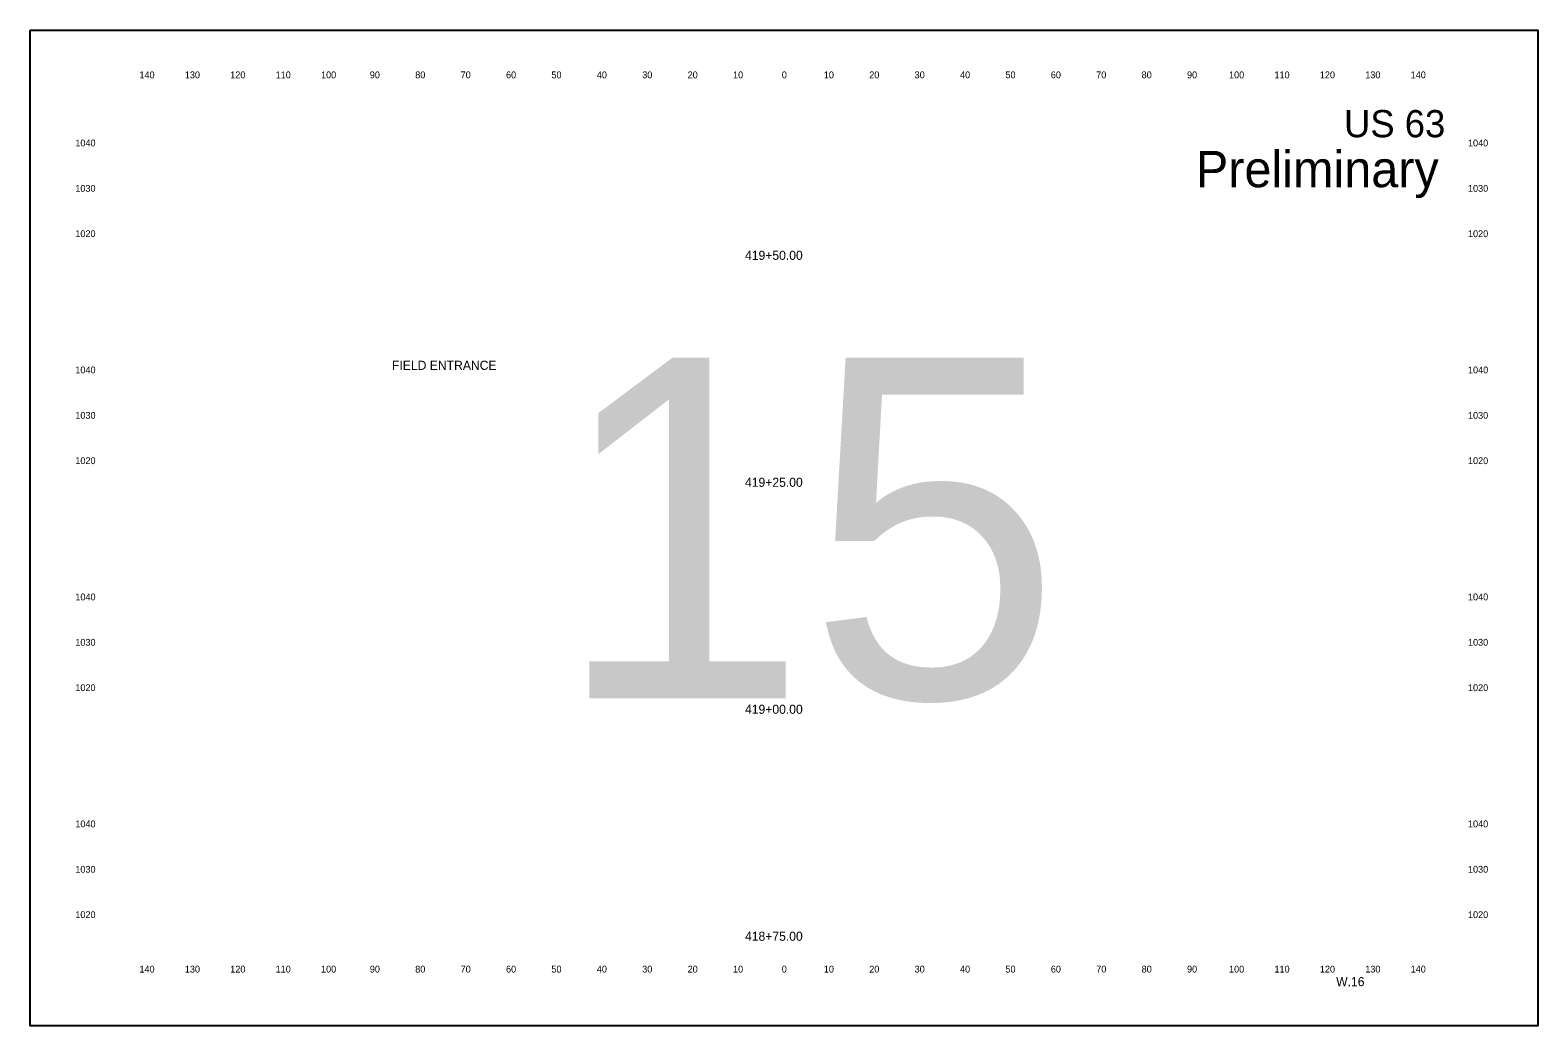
# Model space of a CAD drawing. Extents: x 10123 to 17295, y 9730 to 10181.
# Drawn here: x 15163.2 to 15495.3, y 9730.3 to 9949.6 of the extents above; entities that cross this region are included whole.
import ezdxf

# ---------------------------------------------------------------- set-up
doc = ezdxf.new("R2010")
doc.units = 0
for name, color, linetype in [('dsnTextCpn', 7, 'Continuous'), ('dsnTextCpnTitleSheetLocDesc', 7, 'Continuous'), ('dsnTextCpnTitleSheetPIN', 7, 'Continuous'), ('dsnTextCpnTitleSheetWorkType', 7, 'Continuous')]:
    doc.layers.add(name, color=color, linetype=linetype)

msp = doc.modelspace()

# ---------------------------------------------------------------- linework, layer by layer
at = {"layer": 'dsnTextCpnTitleSheetWorkType'}
msp.add_lwpolyline([(15163.21, 9949.6), (15495.29, 9949.6), (15495.29, 9730.26), (15163.21, 9730.26)], close=True, dxfattribs=at)

# ---------------------------------------------------------------- texts
at = {"layer": 'dsnTextCpn'}
for s, height, p in [('140', 1.5, (15187.27, 9939)), ('130', 1.5, (15197.27, 9939)), ('120', 1.5, (15207.27, 9939)), ('110', 1.5, (15217.27, 9939)), ('100', 1.5, (15227.27, 9939)), ('90', 1.5, (15238.02, 9939)), ('80', 1.5, (15248.02, 9939)), ('70', 1.5, (15258.02, 9939)), ('60', 1.5, (15268.02, 9939)), ('50', 1.5, (15278.02, 9939)), ('40', 1.5, (15288.02, 9939)), ('30', 1.5, (15298.02, 9939)), ('20', 1.5, (15308.02, 9939)), ('10', 1.5, (15318.02, 9939)), ('0', 1.5, (15328.76, 9939)), ('0', 1.5, (15328.76, 9939)), ('10', 1.5, (15338.02, 9939)), ('20', 1.5, (15348.02, 9939)), ('30', 1.5, (15358.02, 9939)), ('40', 1.5, (15368.02, 9939)), ('50', 1.5, (15378.02, 9939)), ('60', 1.5, (15388.02, 9939)), ('70', 1.5, (15398.02, 9939)), ('80', 1.5, (15408.02, 9939)), ('90', 1.5, (15418.02, 9939)), ('100', 1.5, (15427.27, 9939)), ('110', 1.5, (15437.27, 9939)), ('120', 1.5, (15447.27, 9939)), ('130', 1.5, (15457.27, 9939)), ('140', 1.5, (15467.27, 9939)), ('US 63', 6, (15452.6, 9926)), ('1040', 1.5, (15173.15, 9924)), ('1040', 1.5, (15479.9, 9924)), ('1030', 1.5, (15173.15, 9914)), ('1030', 1.5, (15479.9, 9914)), ('1020', 1.5, (15173.15, 9904)), ('1020', 1.5, (15479.9, 9904)), ('419+50.00', 2, (15320.66, 9899)), ('FIELD ENTRANCE', 2, (15242.91, 9874.77)), ('1040', 1.5, (15173.15, 9874)), ('1040', 1.5, (15479.9, 9874)), ('1030', 1.5, (15173.15, 9864)), ('1030', 1.5, (15479.9, 9864)), ('1020', 1.5, (15173.15, 9854)), ('1020', 1.5, (15479.9, 9854)), ('419+25.00', 2, (15320.66, 9849)), ('1040', 1.5, (15173.15, 9824)), ('1040', 1.5, (15479.9, 9824)), ('1030', 1.5, (15173.15, 9814)), ('1030', 1.5, (15479.9, 9814)), ('1020', 1.5, (15173.15, 9804)), ('1020', 1.5, (15479.9, 9804)), ('419+00.00', 2, (15320.66, 9799)), ('1040', 1.5, (15173.15, 9774)), ('1040', 1.5, (15479.9, 9774)), ('1030', 1.5, (15173.15, 9764)), ('1030', 1.5, (15479.9, 9764)), ('1020', 1.5, (15173.15, 9754)), ('1020', 1.5, (15479.9, 9754)), ('418+75.00', 2, (15320.66, 9749)), ('140', 1.5, (15187.27, 9742)), ('130', 1.5, (15197.27, 9742)), ('120', 1.5, (15207.27, 9742)), ('110', 1.5, (15217.27, 9742)), ('100', 1.5, (15227.27, 9742)), ('90', 1.5, (15238.02, 9742)), ('80', 1.5, (15248.02, 9742)), ('70', 1.5, (15258.02, 9742)), ('60', 1.5, (15268.02, 9742)), ('50', 1.5, (15278.02, 9742)), ('40', 1.5, (15288.02, 9742)), ('30', 1.5, (15298.02, 9742)), ('20', 1.5, (15308.02, 9742)), ('10', 1.5, (15318.02, 9742)), ('0', 1.5, (15328.76, 9742)), ('0', 1.5, (15328.76, 9742)), ('10', 1.5, (15338.02, 9742)), ('20', 1.5, (15348.02, 9742)), ('30', 1.5, (15358.02, 9742)), ('40', 1.5, (15368.02, 9742)), ('50', 1.5, (15378.02, 9742)), ('60', 1.5, (15388.02, 9742)), ('70', 1.5, (15398.02, 9742)), ('80', 1.5, (15408.02, 9742)), ('90', 1.5, (15418.02, 9742)), ('100', 1.5, (15427.27, 9742)), ('110', 1.5, (15437.27, 9742)), ('120', 1.5, (15447.27, 9742)), ('130', 1.5, (15457.27, 9742)), ('140', 1.5, (15467.27, 9742))]:
    msp.add_text(s, height=height, dxfattribs=at).set_placement(p)
at = {"layer": 'dsnTextCpnTitleSheetLocDesc'}
msp.add_text('Preliminary', height=8, dxfattribs=at).set_placement((15419.97, 9915))
at = {"layer": 'dsnTextCpnTitleSheetPIN'}
msp.add_text('W.16', height=2, dxfattribs=at).set_placement((15450.87, 9739))
at = {"layer": 'dsnTextCpnTitleSheetWorkType'}
msp.add_text('15', height=75, dxfattribs=at).set_placement((15278.71, 9802.43))

doc.saveas('drawing.dxf')
